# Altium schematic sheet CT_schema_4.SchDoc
size 297 x 173 mm
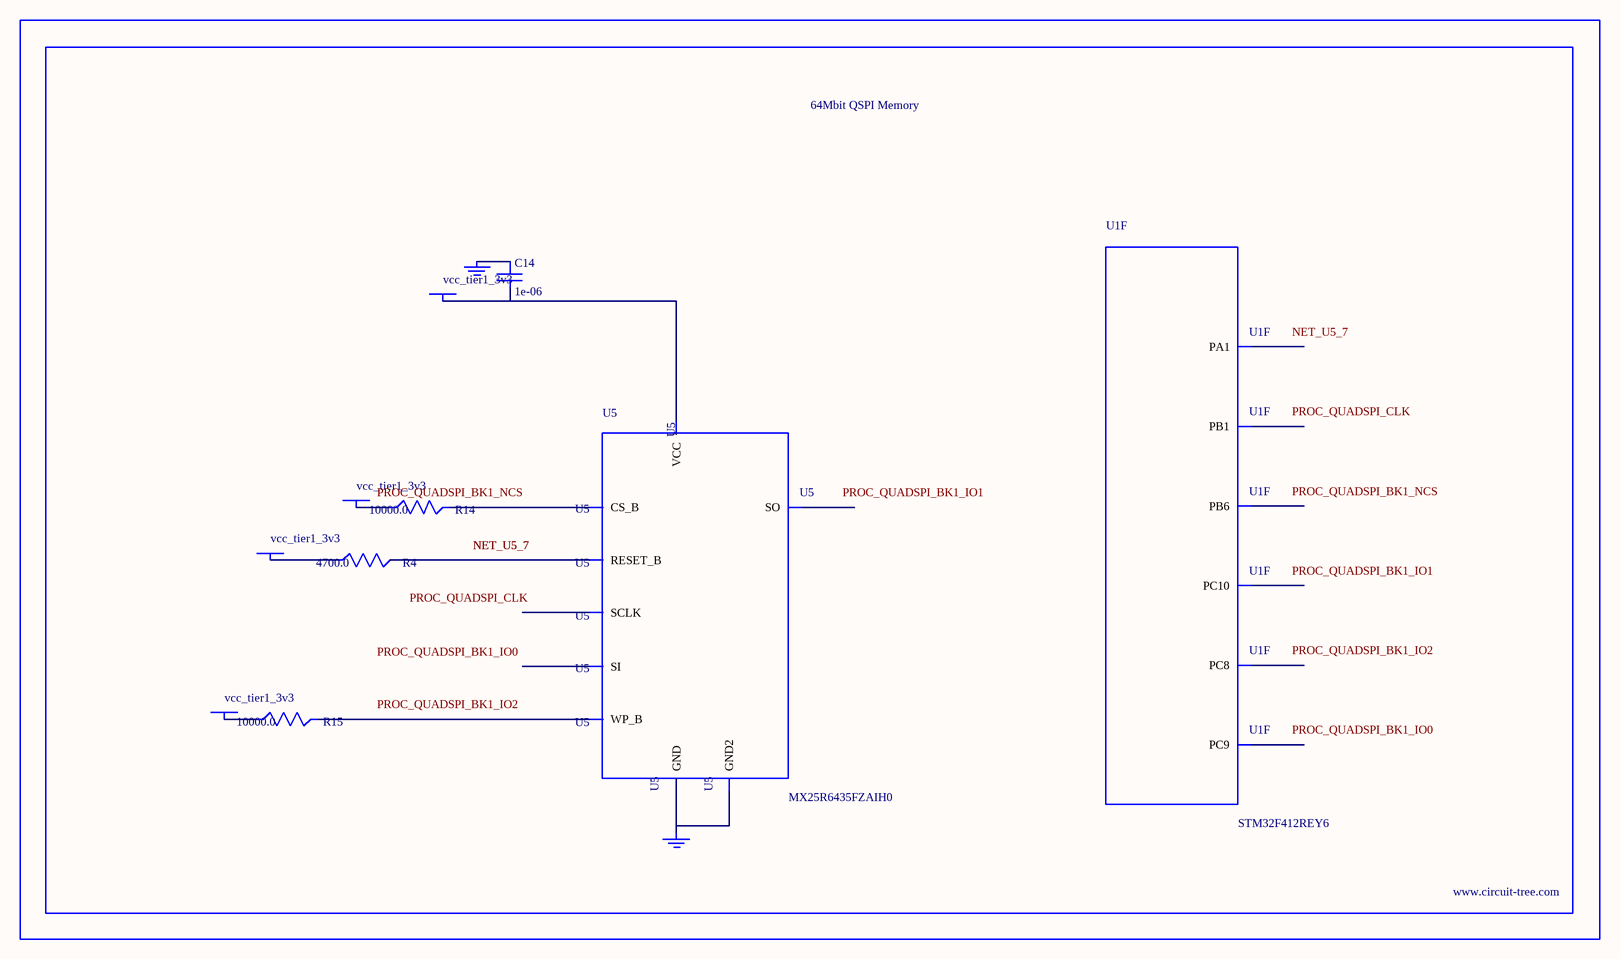
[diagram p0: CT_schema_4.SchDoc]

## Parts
BORDER3  (no value)
C14  1e-06  [C0603]
GND_INSTANCE_3_0  (no value)
GND_INSTANCE_3_1  (no value)
POWER_INSTANCE_3_0  vcc_tier1_3v3
POWER_INSTANCE_3_1  vcc_tier1_3v3
POWER_INSTANCE_3_2  vcc_tier1_3v3
POWER_INSTANCE_3_3  vcc_tier1_3v3
R4  4700.0  [R0603]
R14  10000.0  [R0603]
R15  10000.0  [R0603]
U1  STM32F412REY6  [WLCSP64]  (part F of 7)
U5  MX25R6435FZAIH0  [WSON-8-PAD]

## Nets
NetC14_1: C14.1 GND_INSTANCE_3_0.0(GND)
NetC14_2: C14.2 POWER_INSTANCE_3_2.0(PWR) U5.8(VCC)
NetGND_INSTANCE_3_1_0: GND_INSTANCE_3_1.0(GND) U5.4(GND) U5.PAD(GND2)
NetPOWER_INSTANCE_3_0_0: POWER_INSTANCE_3_0.0(PWR) R14.1
NetPOWER_INSTANCE_3_1_0: POWER_INSTANCE_3_1.0(PWR) R15.1
NetPOWER_INSTANCE_3_3_0: POWER_INSTANCE_3_3.0(PWR) R4.1
NetR4_2: R4.2 U5.7(RESET_B)
NetR14_2: R14.2 U5.1(CS_B)
NetR15_2: R15.2 U5.3(WP_B)

Not connected (* = marked no-connect by the designer): U1 B5(PB6) C3(PC10) E2(PC9) F3(PC8) F4(PB1) G7(PA1); U5 2(SO) 5(SI) 6(SCLK)

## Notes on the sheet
- Labels drawn without touching a wire or pin: NET_U5_7, PROC_QUADSPI_BK1_IO0, PROC_QUADSPI_BK1_IO1, PROC_QUADSPI_BK1_IO2, PROC_QUADSPI_BK1_NCS, PROC_QUADSPI_CLK

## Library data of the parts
BORDER3 = BORDER_PAGE3
C14 = C0603C105K3RACTU
GND_INSTANCE_3_0 GND_INSTANCE_3_1 = GND
POWER_INSTANCE_3_0-POWER_INSTANCE_3_3 = PWR
R4 = RC0603JR-074K7L
R14 R15 = RC0603JR-0710KL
